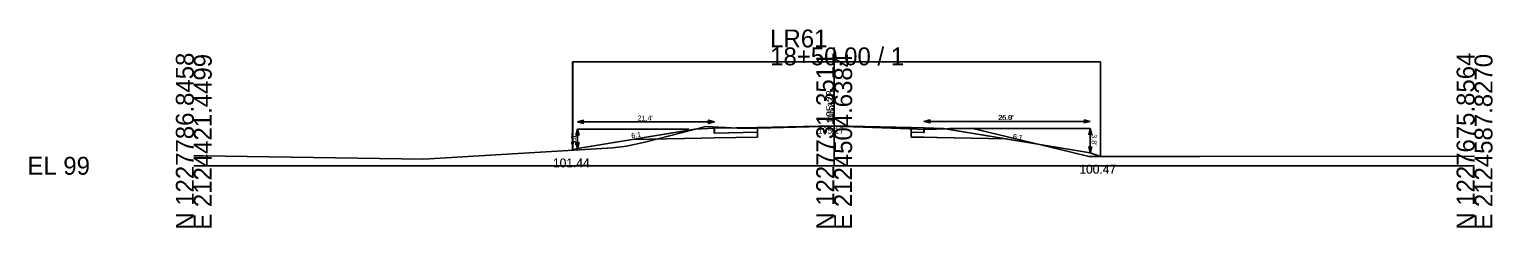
# Model space of a CAD drawing. Extents: x 2126751 to 2128979, y 1225108 to 1234639.
# Drawn here: x 2127750.9 to 2127979.4, y 1233607.5 to 1233638.6 of the extents above; entities that cross this region are included whole.
import ezdxf

# ---------------------------------------------------------------- set-up
doc = ezdxf.new("R2010")
doc.units = 0
for name, color, linetype in [('XS_CELL', 7, 'Continuous'), ('XS_M_DITCH', 7, 'Continuous'), ('XS_P_FINISHED_GRADE', 7, 'Continuous'), ('XS_P_FINISHED_GRADE_ELEV_TX', 7, 'Continuous'), ('XS_P_SUBGRADE_GRANULAR', 7, 'Continuous'), ('XS_P_SUBGRADE_LEVELING', 7, 'Continuous'), ('XS_P_SUBGRADE_PAVEMENT', 7, 'Continuous'), ('XS_P_TX_CLEARZONE', 7, 'Continuous'), ('XS_P_TX_DCH', 7, 'Continuous'), ('XS_P_TX_FS_BS', 7, 'Continuous'), ('XS_X_GROUND', 7, 'Continuous'), ('XS_X_GROUND_TX', 7, 'Continuous')]:
    doc.layers.add(name, color=color, linetype=linetype)

msp = doc.modelspace()

# ---------------------------------------------------------------- linework, layer by layer
at = {"layer": 'XS_CELL'}
for p, q in [((2127876.61, 1233617.21), (2127876.61, 1233635.72)), ((2127776.61, 1233617.21), (2127876.61, 1233617.21)), ((2127876.61, 1233617.21), (2127976.61, 1233617.21))]:
    msp.add_line(p, q, dxfattribs=at)
at = {"layer": 'XS_M_DITCH'}
for p, q in [((2127835.76, 1233619.65), (2127835.76, 1233633.44)), ((2127835.76, 1233633.44), (2127918.19, 1233633.44)), ((2127835.78, 1233619.65), (2127835.78, 1233633.44)), ((2127835.78, 1233633.44), (2127918.22, 1233633.44)), ((2127918.19, 1233633.44), (2127918.19, 1233618.68)), ((2127918.22, 1233633.44), (2127918.22, 1233618.68))]:
    msp.add_line(p, q, dxfattribs=at)
at = {"layer": 'XS_P_FINISHED_GRADE'}
for p, q in [((2127854.87, 1233622.95), (2127836.53, 1233619.9)), ((2127854.91, 1233622.95), (2127836.53, 1233619.9)), ((2127857.89, 1233623.07), (2127854.87, 1233622.95)), ((2127857.92, 1233623.07), (2127854.91, 1233622.95)), ((2127864.61, 1233623.2), (2127857.89, 1233623.07)), ((2127864.61, 1233623.2), (2127857.92, 1233623.07)), ((2127864.61, 1233623.2), (2127876.61, 1233623.44)), ((2127864.61, 1233623.2), (2127876.61, 1233623.44)), ((2127876.61, 1233623.44), (2127888.61, 1233623.2)), ((2127876.61, 1233623.44), (2127888.61, 1233623.2)), ((2127888.61, 1233623.2), (2127890.61, 1233623.16)), ((2127888.61, 1233623.2), (2127890.67, 1233623.16)), ((2127890.61, 1233623.16), (2127893.61, 1233623.04)), ((2127890.67, 1233623.16), (2127893.67, 1233623.04)), ((2127893.61, 1233623.04), (2127916.61, 1233619.21)), ((2127893.67, 1233623.04), (2127916.61, 1233619.22)), ((2127836.53, 1233619.9), (2127835.76, 1233619.65)), ((2127836.53, 1233619.9), (2127835.78, 1233619.65)), ((2127916.61, 1233619.22), (2127918.22, 1233618.68)), ((2127916.61, 1233619.21), (2127918.19, 1233618.68))]:
    msp.add_line(p, q, dxfattribs=at)
at = {"layer": 'XS_P_SUBGRADE_GRANULAR'}
for p, q in [((2127855.89, 1233621.53), (2127845, 1233621.31)), ((2127855.92, 1233621.53), (2127845.04, 1233621.31)), ((2127857.89, 1233621.57), (2127855.89, 1233621.53)), ((2127857.92, 1233621.57), (2127855.92, 1233621.53)), ((2127864.61, 1233621.7), (2127857.89, 1233621.57)), ((2127864.61, 1233621.7), (2127857.92, 1233621.57)), ((2127864.61, 1233621.7), (2127864.61, 1233622.45)), ((2127864.61, 1233621.7), (2127864.61, 1233622.45)), ((2127888.61, 1233621.7), (2127888.61, 1233622.45)), ((2127888.61, 1233621.7), (2127888.61, 1233622.45)), ((2127888.61, 1233621.7), (2127890.61, 1233621.66)), ((2127888.61, 1233621.7), (2127890.67, 1233621.66)), ((2127890.61, 1233621.66), (2127892.61, 1233621.62)), ((2127890.67, 1233621.66), (2127892.67, 1233621.62)), ((2127892.61, 1233621.62), (2127903.43, 1233621.41)), ((2127892.67, 1233621.62), (2127903.49, 1233621.4))]:
    msp.add_line(p, q, dxfattribs=at)
at = {"layer": 'XS_P_SUBGRADE_LEVELING'}
for p, q in [((2127864.61, 1233623.2), (2127864.61, 1233623.1)), ((2127864.61, 1233623.2), (2127864.61, 1233623.1)), ((2127864.61, 1233623.1), (2127866.7, 1233623.15)), ((2127864.61, 1233623.1), (2127866.7, 1233623.15)), ((2127866.7, 1233623.15), (2127876.64, 1233623.38)), ((2127866.7, 1233623.15), (2127876.64, 1233623.38)), ((2127876.64, 1233623.38), (2127885.58, 1233623.09)), ((2127876.64, 1233623.38), (2127885.58, 1233623.09)), ((2127885.58, 1233623.09), (2127888.61, 1233622.98)), ((2127885.58, 1233623.09), (2127888.61, 1233622.98)), ((2127888.61, 1233623.2), (2127888.61, 1233622.98)), ((2127888.61, 1233623.2), (2127888.61, 1233622.98))]:
    msp.add_line(p, q, dxfattribs=at)
at = {"layer": 'XS_P_SUBGRADE_PAVEMENT'}
for p, q in [((2127857.89, 1233622.32), (2127857.89, 1233623.07)), ((2127864.61, 1233622.45), (2127857.89, 1233622.32)), ((2127857.92, 1233622.32), (2127857.92, 1233623.07)), ((2127864.61, 1233622.45), (2127857.92, 1233622.32)), ((2127864.61, 1233622.45), (2127864.61, 1233623.1)), ((2127888.61, 1233622.45), (2127888.61, 1233622.98)), ((2127888.61, 1233622.45), (2127888.61, 1233622.98)), ((2127888.61, 1233622.45), (2127890.61, 1233622.41)), ((2127888.61, 1233622.45), (2127890.67, 1233622.41)), ((2127890.61, 1233622.41), (2127890.61, 1233623.16)), ((2127890.67, 1233622.41), (2127890.67, 1233623.16))]:
    msp.add_line(p, q, dxfattribs=at)
at = {"layer": 'XS_P_TX_CLEARZONE'}
for p, q in [((2127836.53, 1233624.07), (2127837.53, 1233624.32)), ((2127836.53, 1233624.07), (2127837.53, 1233624.32)), ((2127836.53, 1233624.07), (2127837.53, 1233623.82)), ((2127857.89, 1233624.07), (2127836.53, 1233624.07)), ((2127836.53, 1233624.07), (2127837.53, 1233623.82)), ((2127857.92, 1233624.07), (2127836.53, 1233624.07)), ((2127857.89, 1233624.07), (2127856.88, 1233624.32)), ((2127857.89, 1233624.07), (2127856.88, 1233623.82)), ((2127857.92, 1233624.07), (2127856.92, 1233624.32)), ((2127857.92, 1233624.07), (2127856.92, 1233623.82)), ((2127890.61, 1233624.16), (2127891.61, 1233624.41)), ((2127890.61, 1233624.16), (2127891.61, 1233623.91)), ((2127890.61, 1233624.16), (2127916.61, 1233624.16)), ((2127890.67, 1233624.16), (2127891.67, 1233624.41)), ((2127890.67, 1233624.16), (2127891.67, 1233623.91)), ((2127890.67, 1233624.16), (2127916.61, 1233624.16)), ((2127916.61, 1233624.16), (2127915.61, 1233624.41)), ((2127916.61, 1233624.16), (2127915.61, 1233624.41)), ((2127916.61, 1233624.16), (2127915.61, 1233623.91)), ((2127916.61, 1233624.16), (2127915.61, 1233623.91)), ((2127836.53, 1233622.95), (2127836.28, 1233621.95)), ((2127836.53, 1233622.95), (2127836.28, 1233621.95)), ((2127836.53, 1233622.95), (2127836.78, 1233621.95)), ((2127836.53, 1233622.95), (2127836.53, 1233619.9)), ((2127853.87, 1233622.95), (2127836.53, 1233622.95)), ((2127836.53, 1233622.95), (2127836.78, 1233621.95)), ((2127836.53, 1233622.95), (2127836.53, 1233619.9)), ((2127853.91, 1233622.95), (2127836.53, 1233622.95)), ((2127894.61, 1233623.04), (2127916.61, 1233623.04)), ((2127894.67, 1233623.04), (2127916.61, 1233623.04)), ((2127916.61, 1233623.04), (2127916.36, 1233622.04)), ((2127916.61, 1233623.04), (2127916.36, 1233622.04)), ((2127916.61, 1233623.04), (2127916.61, 1233619.21)), ((2127916.61, 1233623.04), (2127916.86, 1233622.04)), ((2127916.61, 1233623.04), (2127916.61, 1233619.22)), ((2127916.61, 1233623.04), (2127916.86, 1233622.04)), ((2127836.53, 1233619.9), (2127836.28, 1233620.9)), ((2127836.53, 1233619.9), (2127836.28, 1233620.9)), ((2127836.53, 1233619.9), (2127836.78, 1233620.9)), ((2127836.53, 1233619.9), (2127836.78, 1233620.9)), ((2127916.61, 1233619.22), (2127916.36, 1233620.22)), ((2127916.61, 1233619.21), (2127916.36, 1233620.21)), ((2127916.61, 1233619.22), (2127916.86, 1233620.22)), ((2127916.61, 1233619.21), (2127916.86, 1233620.21))]:
    msp.add_line(p, q, dxfattribs=at)
at = {"layer": 'XS_X_GROUND'}
for p, q in [((2127847.03, 1233620.9), (2127856.57, 1233623.37)), ((2127856.57, 1233623.37), (2127859.66, 1233623.2)), ((2127859.66, 1233623.2), (2127862.39, 1233623.04)), ((2127862.39, 1233623.04), (2127866.7, 1233623.15)), ((2127866.7, 1233623.15), (2127876.64, 1233623.38)), ((2127876.64, 1233623.38), (2127885.58, 1233623.09)), ((2127885.58, 1233623.09), (2127891.04, 1233622.9)), ((2127891.04, 1233622.9), (2127894.21, 1233623.01)), ((2127894.21, 1233623.01), (2127898.06, 1233623.11)), ((2127898.06, 1233623.11), (2127913.43, 1233619.38)), ((2127812.5, 1233618.26), (2127842.07, 1233620.03)), ((2127842.07, 1233620.03), (2127844.19, 1233620.27)), ((2127844.19, 1233620.27), (2127847.03, 1233620.9)), ((2127913.43, 1233619.38), (2127916.39, 1233618.68)), ((2127776.61, 1233618.78), (2127778.05, 1233618.78)), ((2127778.05, 1233618.78), (2127812.5, 1233618.26)), ((2127916.39, 1233618.68), (2127933.73, 1233618.67)), ((2127933.73, 1233618.67), (2127976.61, 1233618.73))]:
    msp.add_line(p, q, dxfattribs=at)

# ---------------------------------------------------------------- texts
at = {"layer": 'XS_CELL'}
for s, p in [('LR61', (2127866.61, 1233635.72)), ('18+50.00 / 1', (2127866.61, 1233632.92)), ('EL 99', (2127750.61, 1233615.81))]:
    msp.add_text(s, height=2.8, dxfattribs=at).set_placement(p)
for s, p in [('N 1227786.8458', (2127776.61, 1233607.21)), ('E 2124421.4499', (2127779.41, 1233607.21)), ('N 1227731.3511', (2127876.61, 1233607.21)), ('E 2124504.6384', (2127879.41, 1233607.21)), ('N 1227675.8564', (2127976.61, 1233607.21)), ('E 2124587.8270', (2127979.41, 1233607.21))]:
    msp.add_text(s, height=2.8, rotation=90, dxfattribs=at).set_placement(p)
at = {"layer": 'XS_P_FINISHED_GRADE_ELEV_TX'}
for height in [1.25, 1]:
    msp.add_text(' 105.23', height=height, rotation=90, dxfattribs=at).set_placement((2127876.61, 1233623.44))
at = {"layer": 'XS_P_TX_CLEARZONE'}
for s, p in [("21.4'", (2127845.91, 1233624.27)), ("21.4'", (2127845.92, 1233624.27)), ("26.0'", (2127902.21, 1233624.36)), ("25.9'", (2127902.29, 1233624.36))]:
    msp.add_text(s, height=0.8, dxfattribs=at).set_placement(p)
for s, rotation, p in [("3.1'", 90, (2127836.33, 1233620.53)), ("3.0'", 90, (2127836.33, 1233620.4)), ("3.8'", 270, (2127916.81, 1233622.12)), ("3.8'", 270, (2127916.81, 1233622.12))]:
    msp.add_text(s, height=0.8, rotation=rotation, dxfattribs=at).set_placement(p)
at = {"layer": 'XS_P_TX_DCH'}
for s, p in [('101.44', (2127832.69, 1233616.95)), ('101.44', (2127832.71, 1233616.95)), ('100.47', (2127914.89, 1233615.98)), ('100.47', (2127914.92, 1233615.98))]:
    msp.add_text(s, height=1.4, dxfattribs=at).set_placement(p)
at = {"layer": 'XS_P_TX_FS_BS'}
for rotation, p in [(9.4211, (2127844.98, 1233621.51)), (9.4207, (2127845, 1233621.51)), (350.5377, (2127904.45, 1233621.44)), (350.5377, (2127904.48, 1233621.44))]:
    msp.add_text('6:1', height=0.8, rotation=rotation, dxfattribs=at).set_placement(p)
at = {"layer": 'XS_X_GROUND_TX'}
msp.add_text('105.17', height=1, dxfattribs=at).set_placement((2127874.05, 1233622.22))

doc.saveas('drawing.dxf')
